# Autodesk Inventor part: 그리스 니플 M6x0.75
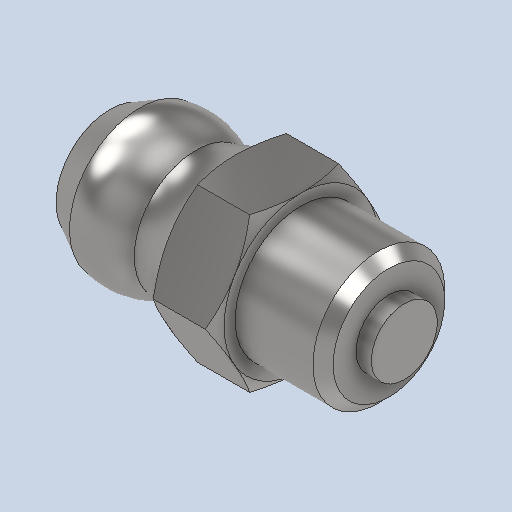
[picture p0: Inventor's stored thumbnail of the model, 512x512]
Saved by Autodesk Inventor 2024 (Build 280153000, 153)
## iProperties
Created: 2025-10
Part Number: 그리스 니플 M6x0.75
Material: 강철, 연강
Description: 윤활 니플, 원추 유형 A
Document SubType Name: Modeling
Designer: EDU03
Density: 7.85 g/cm^3
Appearance: 기본값
Author: jhkim
Sending System: Autodesk Inventor 2026
Preprocessor: ST-DEVELOPER v20.1
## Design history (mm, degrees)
feature "Solid1"
node "솔리드1"
